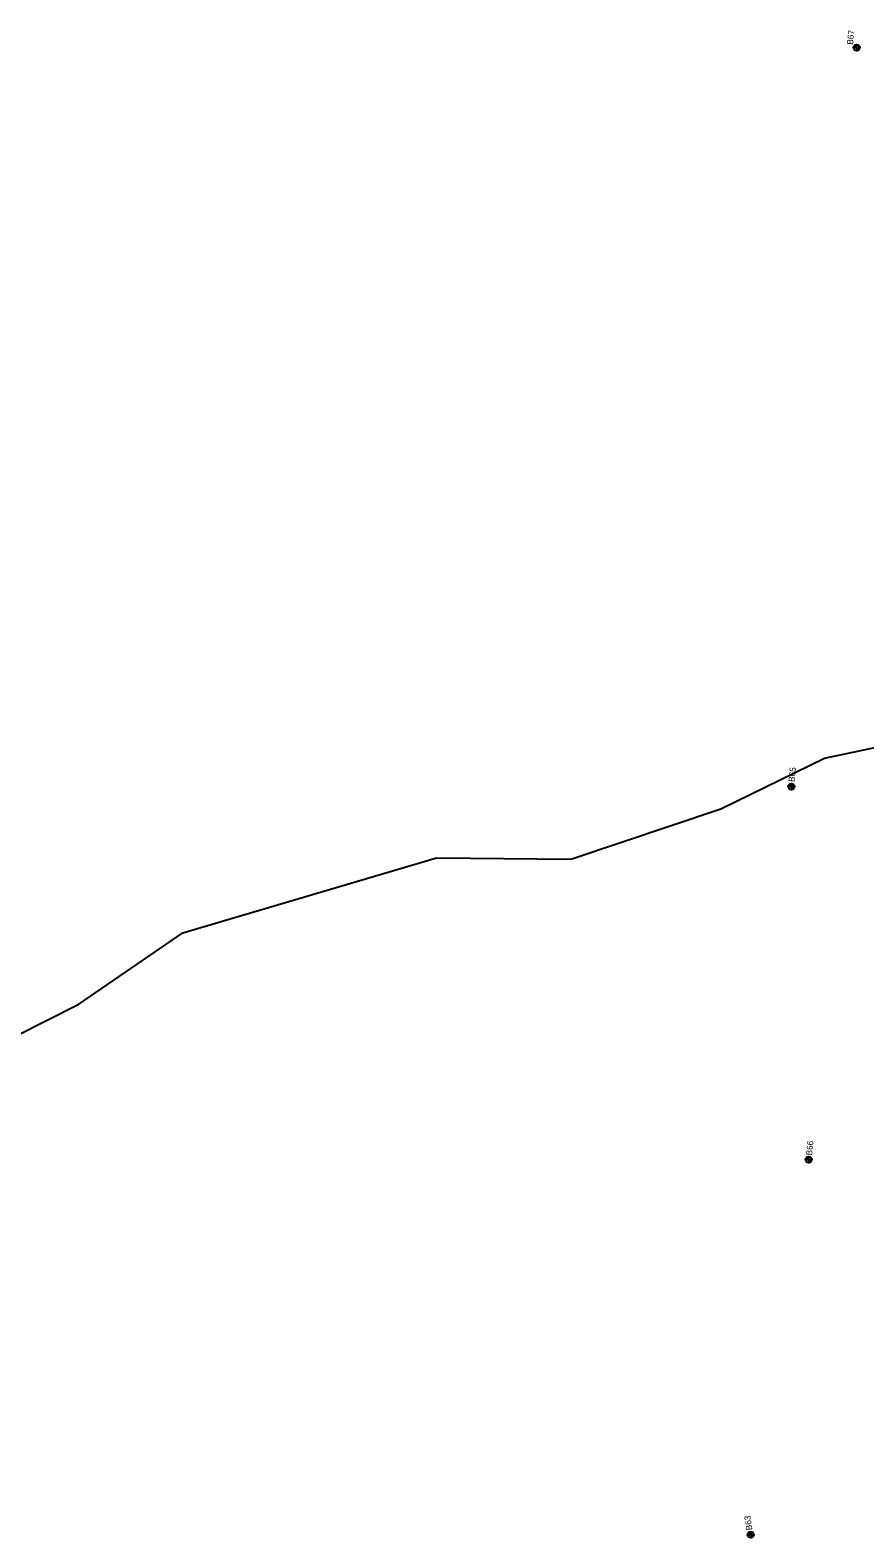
# Model space of a CAD drawing. Extents: x 331323 to 388339, y 121519 to 205315.
# Drawn here: x 358185 to 359534, y 165252 to 167689 of the extents above; entities that cross this region are included whole.
import ezdxf

# ---------------------------------------------------------------- set-up
doc = ezdxf.new("R2010")
doc.units = 0
for name, color, linetype in [('E_SOIL_BORE1 [KAPUR_CADDS_LEVELS]', 7, 'Continuous'), ('E_SOIL_BORE2 [KAPUR_CADDS_LEVELS]', 7, 'Continuous'), ('Level 57', 7, 'Continuous'), ('P_MARK', 7, 'Continuous')]:
    doc.layers.add(name, color=color, linetype=linetype)

msp = doc.modelspace()

# ---------------------------------------------------------------- linework, layer by layer
at = {"layer": 'Level 57'}
msp.add_lwpolyline([(356837, 166027.8), (356868.6, 165844.1), (356918.1, 165777), (357308.5, 165615.1), (357525.4, 165613.2), (357684.6, 165695.1), (357802.6, 165835.7), (358004.2, 165983.9), (358263.9, 166114.8), (358431.8, 166230), (358841.5, 166351.3), (359058.4, 166349.3), (359301, 166430.5), (359468.5, 166512.3), (359618.9, 166544.3)], dxfattribs=at)
at = {"layer": 'P_MARK'}
for p, q in [((359520.3, 167666.3), (359520.3, 167656.3)), ((359515.3, 167661.3), (359525.3, 167661.3)), ((359415, 166471.5), (359415, 166461.5)), ((359410, 166466.5), (359420, 166466.5)), ((359437.8, 165863.3), (359447.8, 165863.3)), ((359442.8, 165868.3), (359442.8, 165858.3)), ((359344.2, 165256.8), (359354.2, 165256.8)), ((359349.2, 165261.8), (359349.2, 165251.8))]:
    msp.add_line(p, q, dxfattribs=at)
for centre in [(359520.3, 167661.3), (359415, 166466.5), (359442.8, 165863.3), (359349.2, 165256.8)]:
    msp.add_circle(centre, 5, dxfattribs=at)
for centre, radius, start, end in [((359520.3, 167661.3), 4.5, 89.9869, 179.9869), ((359520.3, 167661.3), 4, 89.9869, 179.9869), ((359520.3, 167661.3), 3.5, 89.9869, 179.9869), ((359520.3, 167661.3), 3, 89.9869, 179.9869), ((359520.3, 167661.3), 2.5, 89.9869, 179.9869), ((359520.3, 167661.3), 2, 89.9869, 179.9869), ((359520.3, 167661.3), 1.5, 89.9869, 179.9869), ((359520.3, 167661.3), 1, 89.9869, 179.9869), ((359520.3, 167661.3), 0.5, 89.9869, 179.9869), ((359520.3, 167661.3), 4.5, 269.9869, 359.9869), ((359520.3, 167661.3), 4, 269.9869, 359.9869), ((359520.3, 167661.3), 3.5, 269.9869, 359.9869), ((359520.3, 167661.3), 3, 269.9869, 359.9869), ((359520.3, 167661.3), 2.5, 269.9869, 359.9869), ((359520.3, 167661.3), 2, 269.9869, 359.9869), ((359520.3, 167661.3), 1.5, 269.9869, 359.9869), ((359520.3, 167661.3), 1, 269.9869, 359.9869), ((359520.3, 167661.3), 0.5, 269.9869, 359.9869), ((359415, 166466.5), 4.5, 89.9869, 179.9869), ((359415, 166466.5), 4, 89.9869, 179.9869), ((359415, 166466.5), 3.5, 89.9869, 179.9869), ((359415, 166466.5), 3, 89.9869, 179.9869), ((359415, 166466.5), 2.5, 89.9869, 179.9869), ((359415, 166466.5), 2, 89.9869, 179.9869), ((359415, 166466.5), 1.5, 89.9869, 179.9869), ((359415, 166466.5), 1, 89.9869, 179.9869), ((359415, 166466.5), 0.5, 89.9869, 179.9869), ((359415, 166466.5), 4.5, 269.9869, 359.9869), ((359415, 166466.5), 4, 269.9869, 359.9869), ((359415, 166466.5), 3.5, 269.9869, 359.9869), ((359415, 166466.5), 3, 269.9869, 359.9869), ((359415, 166466.5), 2.5, 269.9869, 359.9869), ((359415, 166466.5), 2, 269.9869, 359.9869), ((359415, 166466.5), 1.5, 269.9869, 359.9869), ((359415, 166466.5), 1, 269.9869, 359.9869), ((359415, 166466.5), 0.5, 269.9869, 359.9869), ((359442.8, 165863.3), 4.5, 89.9869, 179.9869), ((359442.8, 165863.3), 4, 89.9869, 179.9869), ((359442.8, 165863.3), 3.5, 89.9869, 179.9869), ((359442.8, 165863.3), 3, 89.9869, 179.9869), ((359442.8, 165863.3), 2.5, 89.9869, 179.9869), ((359442.8, 165863.3), 2, 89.9869, 179.9869), ((359442.8, 165863.3), 1.5, 89.9869, 179.9869), ((359442.8, 165863.3), 1, 89.9869, 179.9869), ((359442.8, 165863.3), 0.5, 89.9869, 179.9869), ((359442.8, 165863.3), 4.5, 269.9869, 359.9869), ((359442.8, 165863.3), 4, 269.9869, 359.9869), ((359442.8, 165863.3), 3.5, 269.9869, 359.9869), ((359442.8, 165863.3), 3, 269.9869, 359.9869), ((359442.8, 165863.3), 2.5, 269.9869, 359.9869), ((359442.8, 165863.3), 2, 269.9869, 359.9869), ((359442.8, 165863.3), 1.5, 269.9869, 359.9869), ((359442.8, 165863.3), 1, 269.9869, 359.9869), ((359442.8, 165863.3), 0.5, 269.9869, 359.9869), ((359349.2, 165256.8), 4.5, 89.9869, 179.9869), ((359349.2, 165256.8), 4, 89.9869, 179.9869), ((359349.2, 165256.8), 3.5, 89.9869, 179.9869), ((359349.2, 165256.8), 3, 89.9869, 179.9869), ((359349.2, 165256.8), 2.5, 89.9869, 179.9869), ((359349.2, 165256.8), 2, 89.9869, 179.9869), ((359349.2, 165256.8), 1.5, 89.9869, 179.9869), ((359349.2, 165256.8), 1, 89.9869, 179.9869), ((359349.2, 165256.8), 0.5, 89.9869, 179.9869), ((359349.2, 165256.8), 4.5, 269.9869, 359.9869), ((359349.2, 165256.8), 4, 269.9869, 359.9869), ((359349.2, 165256.8), 3.5, 269.9869, 359.9869), ((359349.2, 165256.8), 3, 269.9869, 359.9869), ((359349.2, 165256.8), 2.5, 269.9869, 359.9869), ((359349.2, 165256.8), 2, 269.9869, 359.9869), ((359349.2, 165256.8), 1.5, 269.9869, 359.9869), ((359349.2, 165256.8), 1, 269.9869, 359.9869), ((359349.2, 165256.8), 0.5, 269.9869, 359.9869)]:
    msp.add_arc(centre, radius, start, end, dxfattribs=at)

# ---------------------------------------------------------------- texts
at = {"layer": 'E_SOIL_BORE1 [KAPUR_CADDS_LEVELS]'}
for s, rotation, p in [('B67', 84.1728, (359514.4, 167665.5)), ('B63', 98.5151, (359352.1, 165264.9))]:
    msp.add_text(s, height=10, rotation=rotation, dxfattribs=at).set_placement(p)
at = {"layer": 'E_SOIL_BORE2 [KAPUR_CADDS_LEVELS]'}
for s, p in [('B65', (359420.1, 166473.6)), ('B66', (359448.3, 165869.7))]:
    msp.add_text(s, height=10, rotation=84.1728, dxfattribs=at).set_placement(p)

doc.saveas('drawing.dxf')
